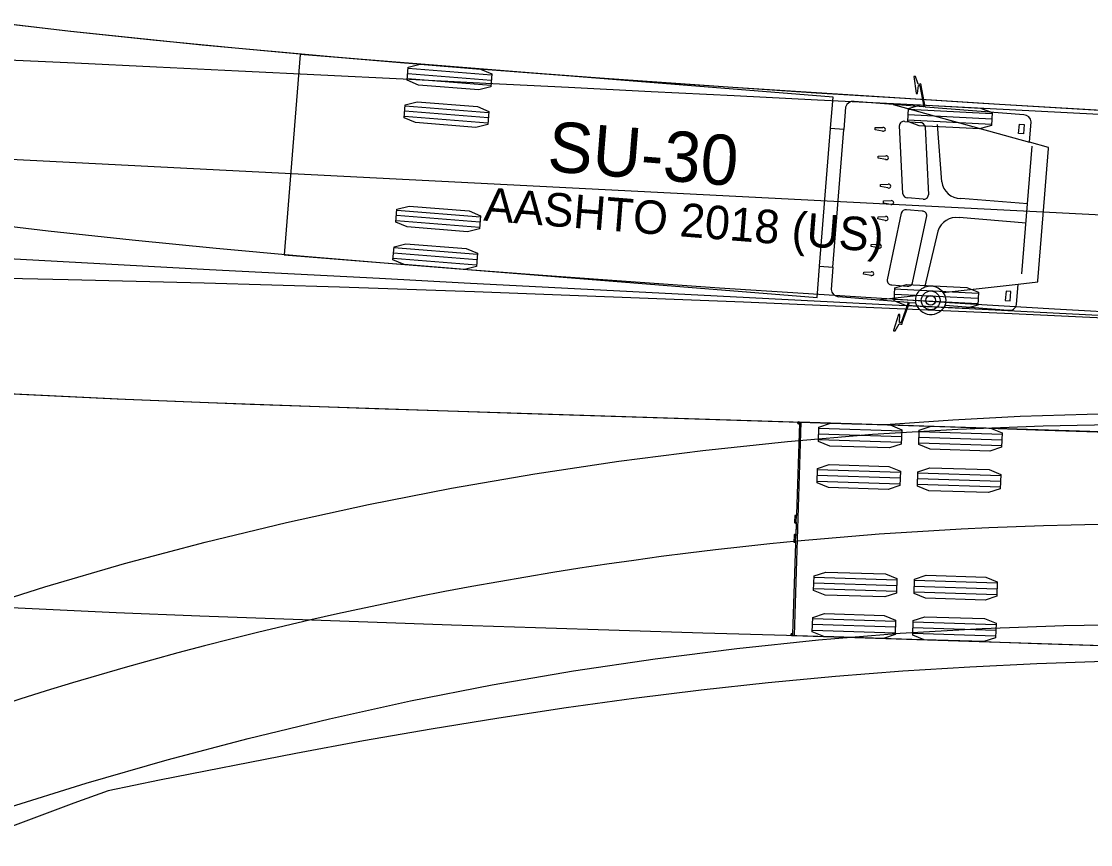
# Model space of a CAD drawing. Extents: x 260275 to 261282, y 610916 to 614143.
# Drawn here: x 261085.23 to 261127.81, y 611586.21 to 611618.98 of the extents above; entities that cross this region are included whole.
import ezdxf

# ---------------------------------------------------------------- set-up
doc = ezdxf.new("R2010")
doc.units = 0
doc.layers.add('UT_X_Water_Cells', color=7, linetype='Continuous')

msp = doc.modelspace()

# ---------------------------------------------------------------- linework, layer by layer
at = {"layer": 'UT_X_Water_Cells'}
for p, q in [((261103.944, 611616.631), (261100.621, 611616.896)), ((261103.96, 611616.838), (261100.637, 611617.103)), ((261103.927, 611616.423), (261100.604, 611616.688)), ((261103.841, 611615.343), (261100.518, 611615.608)), ((261119.945, 611615.672), (261125.371, 611614.171)), ((261103.808, 611614.928), (261100.485, 611615.193)), ((261103.824, 611615.135), (261100.502, 611615.4)), ((261123.871, 611615.089), (261120.542, 611615.258)), ((261123.882, 611615.297), (261120.553, 611615.466)), ((261119.227, 611614.667), (261119.234, 611614.75)), ((261119.234, 611614.75), (261119.536, 611614.761)), ((261120.333, 611612.119), (261120.196, 611614.833)), ((261120.412, 611614.998), (261121.027, 611614.949)), ((261123.861, 611614.881), (261120.532, 611615.05)), ((261121.216, 611614.782), (261121.352, 611612.068)), ((261121.882, 611612.59), (261121.718, 611614.874)), ((261124.941, 611614.517), (261124.972, 611614.894)), ((261124.972, 611614.894), (261125.165, 611614.879)), ((261125.165, 611614.879), (261125.135, 611614.501)), ((261066.343, 611614.434), (261269.731, 611604.069)), ((261117.017, 611609.238), (261117.454, 611614.713)), ((261117.547, 611609.196), (261117.984, 611614.671)), ((261119.523, 611614.608), (261119.227, 611614.667)), ((261125.135, 611614.501), (261124.941, 611614.517)), ((261125.076, 611608.923), (261125.482, 611614.012)), ((261119.348, 611613.537), (261119.355, 611613.619)), ((261119.658, 611613.477), (261119.348, 611613.537)), ((261119.355, 611613.619), (261119.67, 611613.631)), ((261119.441, 611612.409), (261119.448, 611612.491)), ((261119.737, 611612.349), (261119.441, 611612.409)), ((261119.448, 611612.491), (261119.749, 611612.503)), ((261119.557, 611611.749), (261119.564, 611611.831)), ((261119.853, 611611.689), (261119.557, 611611.749)), ((261119.564, 611611.831), (261119.866, 611611.843)), ((261121.137, 611611.903), (261120.522, 611611.952)), ((261125.299, 611611.717), (261122.639, 611611.929)), ((261103.51, 611611.19), (261100.187, 611611.455)), ((261120.271, 611611.343), (261119.706, 611608.685)), ((261121.099, 611611.429), (261120.484, 611611.478)), ((261103.476, 611610.774), (261100.154, 611611.039)), ((261103.493, 611610.982), (261100.17, 611611.247)), ((261119.338, 611611.116), (261119.345, 611611.199)), ((261119.634, 611611.057), (261119.338, 611611.116)), ((261119.345, 611611.199), (261119.646, 611611.211)), ((261120.721, 611608.574), (261121.286, 611611.232)), ((261125.238, 611610.953), (261122.578, 611611.166)), ((261121.726, 611610.633), (261121.199, 611608.392)), ((261119.067, 611610.017), (261119.074, 611610.099)), ((261119.074, 611610.099), (261119.376, 611610.111)), ((261103.374, 611609.487), (261100.051, 611609.752)), ((261103.39, 611609.694), (261100.068, 611609.959)), ((261119.363, 611609.958), (261119.067, 611610.017)), ((261103.357, 611609.279), (261100.034, 611609.544)), ((261118.769, 611608.92), (261118.775, 611609.002)), ((261119.065, 611608.861), (261118.769, 611608.92)), ((261118.775, 611609.002), (261119.077, 611609.014)), ((261119.893, 611608.488), (261120.508, 611608.439)), ((261121.943, 611608.188), (261124.92, 611608.518)), ((261119.325, 611607.897), (261120.865, 611608.068)), ((261123.325, 611607.943), (261119.996, 611608.113)), ((261123.336, 611608.151), (261120.007, 611608.321)), ((261124.441, 611608.245), (261124.411, 611607.868)), ((261124.635, 611608.23), (261124.441, 611608.245)), ((261124.605, 611607.852), (261124.635, 611608.23)), ((261123.315, 611607.735), (261119.986, 611607.905)), ((261122.019, 611607.682), (261124.533, 611607.481)), ((261124.411, 611607.868), (261124.605, 611607.852)), ((261116.013, 611594.53), (261116.286, 611603.026)), ((261120.278, 611602.439), (261116.98, 611602.545)), ((261120.286, 611602.668), (261116.988, 611602.774)), ((261124.276, 611602.31), (261120.978, 611602.416)), ((261124.284, 611602.539), (261120.985, 611602.645)), ((261120.271, 611602.21), (261116.973, 611602.316)), ((261124.269, 611602.081), (261120.971, 611602.187)), ((261120.233, 611601.019), (261116.935, 611601.125)), ((261120.225, 611600.79), (261116.927, 611600.896)), ((261124.223, 611600.661), (261120.925, 611600.767)), ((261124.231, 611600.89), (261120.932, 611600.996)), ((261120.218, 611600.561), (261116.92, 611600.667)), ((261124.216, 611600.432), (261120.918, 611600.538)), ((261116.088, 611599.04), (261116.071, 611598.517)), ((261116.088, 611599.046), (261116.096, 611599.311)), ((261116.079, 611598.78), (261116.15, 611598.778)), ((261116.062, 611598.249), (261116.071, 611598.515)), ((261120.095, 611596.738), (261116.797, 611596.844)), ((261120.088, 611596.509), (261116.79, 611596.615)), ((261124.086, 611596.38), (261120.787, 611596.486)), ((261124.093, 611596.609), (261120.795, 611596.715)), ((261120.08, 611596.28), (261116.782, 611596.386)), ((261124.078, 611596.151), (261120.78, 611596.257)), ((261120.042, 611595.089), (261116.744, 611595.195)), ((261120.027, 611594.63), (261116.729, 611594.736)), ((261120.035, 611594.859), (261116.737, 611594.966)), ((261124.033, 611594.731), (261120.734, 611594.837)), ((261124.04, 611594.96), (261120.742, 611595.066)), ((261124.025, 611594.502), (261120.727, 611594.608))]:
    msp.add_line(p, q, dxfattribs=at)
for points in [[(261083.936, 611618.979), (261087.195, 611618.596), (261090.467, 611618.245), (261093.749, 611617.921), (261097.038, 611617.62), (261100.335, 611617.339), (261103.637, 611617.075), (261106.943, 611616.825), (261110.253, 611616.587), (261113.566, 611616.359), (261116.881, 611616.141), (261120.199, 611615.93), (261123.519, 611615.725), (261126.839, 611615.525), (261130.162, 611615.33)], [(261084.592, 611618.899), (261087.2, 611618.596), (261092.438, 611618.047), (261097.699, 611617.562), (261102.977, 611617.126), (261108.268, 611616.728), (261113.567, 611616.359), (261124.183, 611615.684), (261134.814, 611615.063), (261156.1, 611613.904), (261198.699, 611611.699)], [(261084.127, 611617.473), (261087.366, 611617.325), (261090.618, 611617.171), (261093.882, 611617.013), (261097.154, 611616.853), (261100.436, 611616.69), (261103.724, 611616.526), (261107.018, 611616.36), (261110.318, 611616.194), (261113.622, 611616.027), (261116.929, 611615.859), (261120.24, 611615.691), (261123.554, 611615.522), (261126.87, 611615.354), (261130.188, 611615.185)], [(261118.055, 611615.567), (261117.984, 611614.674), (261117.98, 611614.671), (261117.455, 611614.713), (261117.455, 611614.724), (261117.553, 611615.963), (261096.334, 611617.656), (261096.016, 611613.668), (261095.698, 611609.681), (261116.917, 611607.988), (261117.016, 611609.227), (261117.018, 611609.238), (261117.543, 611609.196), (261117.547, 611609.193), (261117.476, 611608.3)], [(261120.993, 611616.471), (261120.946, 611616.475), (261120.945, 611616.476), (261120.838, 611616.78), (261120.773, 611616.785), (261120.773, 611616.782), (261120.859, 611616.117), (261120.86, 611616.114), (261120.916, 611616.11), (261120.916, 611616.112), (261120.95, 611616.428), (261120.95, 611616.429), (261120.994, 611616.424)], [(261125.154, 611615.257), (261121.233, 611615.569), (261121.222, 611615.577), (261121.062, 611616.424), (261121.062, 611616.425)], [(261121.014, 611616.412), (261121.014, 611616.411), (261121.168, 611615.579), (261121.155, 611615.575), (261118.39, 611615.796)], [(261124.856, 611607.71), (261124.92, 611608.515), (261124.925, 611608.519), (261125.706, 611608.606), (261125.711, 611608.648), (261125.921, 611611.283), (261126.131, 611613.918), (261126.133, 611613.96), (261125.376, 611614.17), (261125.371, 611614.175), (261125.436, 611614.98)], [(261082.953, 611611.04), (261086.299, 611610.647), (261089.645, 611610.287), (261092.99, 611609.957), (261096.333, 611609.651), (261099.675, 611609.366), (261103.015, 611609.099), (261106.354, 611608.846), (261109.692, 611608.607), (261113.028, 611608.378), (261116.364, 611608.158), (261119.698, 611607.945), (261123.032, 611607.739), (261126.365, 611607.539), (261129.697, 611607.344)], [(261082.504, 611609.665), (261085.925, 611609.474), (261089.332, 611609.288), (261092.728, 611609.107), (261096.113, 611608.928), (261099.491, 611608.751), (261102.86, 611608.576), (261106.224, 611608.402), (261109.582, 611608.23), (261112.936, 611608.057), (261116.286, 611607.886), (261119.633, 611607.715), (261122.977, 611607.544), (261126.319, 611607.373), (261129.658, 611607.203)], [(261188.635, 611604.191), (261146.014, 611606.327), (261124.68, 611607.337), (261113.994, 611607.802), (261103.282, 611608.218), (261097.908, 611608.4), (261092.517, 611608.561), (261087.099, 611608.697), (261081.645, 611608.809)], [(261117.77, 611608.021), (261120.535, 611607.8), (261120.547, 611607.794), (261120.263, 611606.997), (261120.263, 611606.997)], [(261120.309, 611606.976), (261120.309, 611606.977), (261120.6, 611607.788), (261120.613, 611607.794), (261120.84, 611607.776)], [(261120.242, 611606.987), (261120.198, 611606.99), (261120.197, 611606.991), (261120.214, 611607.308), (261120.214, 611607.31), (261120.158, 611607.315), (261120.157, 611607.312), (261119.966, 611606.669), (261119.966, 611606.666), (261120.03, 611606.661), (261120.185, 611606.945), (261120.186, 611606.945), (261120.233, 611606.942)], [(261082.788, 611604.259), (261086.071, 611604.093), (261089.369, 611603.944), (261092.677, 611603.81), (261095.993, 611603.685), (261099.315, 611603.569), (261102.642, 611603.458), (261105.971, 611603.35), (261109.303, 611603.245), (261112.637, 611603.14), (261115.972, 611603.035), (261119.308, 611602.929), (261122.645, 611602.821), (261125.982, 611602.712), (261129.32, 611602.6)], [(261083.782, 611604.207), (261089.045, 611603.958), (261094.338, 611603.746), (261104.974, 611603.382), (261118.308, 611602.962), (261119.643, 611602.935), (261122.321, 611603.122), (261124.998, 611603.258), (261127.674, 611603.345), (261130.349, 611603.384), (261133.023, 611603.374), (261135.695, 611603.316), (261138.365, 611603.211), (261141.033, 611603.058), (261151.703, 611602.341), (261162.373, 611601.688), (261170.375, 611601.234), (261181.049, 611600.761)], [(261083.033, 611595.474), (261086.164, 611596.467), (261089.337, 611597.392), (261092.547, 611598.247), (261095.789, 611599.033), (261099.061, 611599.75), (261102.359, 611600.395), (261105.679, 611600.97), (261109.019, 611601.472), (261112.375, 611601.902), (261115.745, 611602.258), (261119.127, 611602.541), (261122.518, 611602.749), (261125.917, 611602.883), (261129.32, 611602.942)], [(261115.943, 611594.555), (261115.943, 611594.532), (261163.847, 611592.993), (261163.984, 611597.24), (261164.121, 611601.488), (261116.216, 611603.028), (261116.215, 611603.006)], [(261116.214, 611602.982), (261116.214, 611602.981), (261116.098, 611599.347), (261116.096, 611599.311), (261116.026, 611599.313), (261116.026, 611599.312), (261116.017, 611599.046)], [(261116, 611598.519), (261115.992, 611598.253), (261115.992, 611598.252), (261116.062, 611598.249), (261116.061, 611598.213), (261115.944, 611594.58), (261115.944, 611594.579)], [(261082.326, 611595.772), (261085.664, 611595.603), (261089.004, 611595.452), (261092.345, 611595.316), (261095.686, 611595.191), (261099.025, 611595.074), (261102.363, 611594.962), (261105.7, 611594.855), (261109.035, 611594.749), (261112.37, 611594.644), (261115.704, 611594.539), (261119.037, 611594.433), (261122.369, 611594.326), (261125.701, 611594.216), (261129.033, 611594.105)], [(261084.586, 611587.644), (261087.813, 611588.648), (261091.04, 611589.579), (261094.269, 611590.436), (261097.5, 611591.219), (261100.735, 611591.927), (261103.975, 611592.561), (261107.218, 611593.121), (261110.466, 611593.607), (261113.717, 611594.019), (261116.971, 611594.357), (261120.227, 611594.622), (261123.485, 611594.814), (261126.742, 611594.933), (261129.999, 611594.979)], [(261176.331, 611592.251), (261165.672, 611592.71), (261155.013, 611593.147), (261144.355, 611593.559), (261139.021, 611593.616), (261133.684, 611593.602), (261131.015, 611593.563), (261128.345, 611593.497), (261125.674, 611593.402), (261123.002, 611593.274), (261120.328, 611593.107), (261117.653, 611592.897), (261114.976, 611592.646), (261112.297, 611592.353), (261109.616, 611592.021), (261106.932, 611591.652), (261104.246, 611591.246), (261101.555, 611590.808), (261098.86, 611590.337), (261096.16, 611589.839), (261090.739, 611588.77), (261088.696, 611588.35), (261087.322, 611587.861), (261084.559, 611586.816)]]:
    msp.add_lwpolyline(points, dxfattribs=at)
for points in [[(261103.964, 611616.89), (261103.923, 611616.371), (261103.445, 611616.252), (261101.053, 611616.443), (261100.6, 611616.637), (261100.641, 611617.155), (261101.119, 611617.274), (261103.512, 611617.083)], [(261103.845, 611615.395), (261103.804, 611614.876), (261103.326, 611614.757), (261100.934, 611614.948), (261100.481, 611615.141), (261100.522, 611615.66), (261101, 611615.779), (261103.392, 611615.588)], [(261123.885, 611615.349), (261123.858, 611614.829), (261123.384, 611614.697), (261120.987, 611614.819), (261120.529, 611614.999), (261120.556, 611615.518), (261121.03, 611615.651), (261123.427, 611615.529)], [(261103.514, 611611.241), (261103.472, 611610.723), (261102.995, 611610.604), (261100.602, 611610.795), (261100.15, 611610.988), (261100.191, 611611.506), (261100.669, 611611.625), (261103.061, 611611.434)], [(261103.394, 611609.746), (261103.353, 611609.228), (261102.875, 611609.108), (261100.483, 611609.299), (261100.03, 611609.493), (261100.072, 611610.011), (261100.549, 611610.13), (261102.942, 611609.939)], [(261123.339, 611608.203), (261123.312, 611607.683), (261122.838, 611607.551), (261120.441, 611607.673), (261119.983, 611607.854), (261120.01, 611608.373), (261120.484, 611608.506), (261122.881, 611608.383)], [(261120.288, 611602.725), (261120.269, 611602.153), (261119.802, 611601.996), (261117.427, 611602.072), (261116.971, 611602.259), (261116.989, 611602.831), (261117.457, 611602.988), (261119.831, 611602.912)], [(261124.286, 611602.596), (261124.267, 611602.025), (261123.8, 611601.867), (261121.425, 611601.943), (261120.969, 611602.131), (261120.987, 611602.702), (261121.455, 611602.86), (261123.829, 611602.783)], [(261120.235, 611601.076), (261120.216, 611600.504), (261119.749, 611600.347), (261117.374, 611600.423), (261116.918, 611600.61), (261116.936, 611601.182), (261117.404, 611601.339), (261119.778, 611601.263)], [(261124.233, 611600.947), (261124.214, 611600.375), (261123.747, 611600.218), (261121.372, 611600.294), (261120.916, 611600.481), (261120.934, 611601.053), (261121.402, 611601.211), (261123.776, 611601.134)], [(261120.097, 611596.794), (261120.079, 611596.223), (261119.611, 611596.065), (261117.237, 611596.142), (261116.78, 611596.329), (261116.799, 611596.901), (261117.266, 611597.058), (261119.641, 611596.982)], [(261124.095, 611596.666), (261124.077, 611596.094), (261123.609, 611595.937), (261121.234, 611596.013), (261120.778, 611596.2), (261120.797, 611596.772), (261121.264, 611596.929), (261123.639, 611596.853)], [(261120.044, 611595.145), (261120.026, 611594.574), (261119.558, 611594.416), (261117.184, 611594.493), (261116.727, 611594.68), (261116.746, 611595.251), (261117.213, 611595.409), (261119.588, 611595.332)], [(261124.042, 611595.017), (261124.024, 611594.445), (261123.556, 611594.288), (261121.181, 611594.364), (261120.725, 611594.551), (261120.744, 611595.123), (261121.211, 611595.28), (261123.586, 611595.204)]]:
    msp.add_lwpolyline(points, close=True, dxfattribs=at)
for centre, radius in [((261121.441, 611607.873), 0.374), ((261121.441, 611607.873), 0.193), ((261116.181, 611602.995), 0.0266), ((261115.91, 611594.568), 0.0266)]:
    msp.add_circle(centre, radius, dxfattribs=at)
for centre, radius, start, end in [((261121.027, 611616.447), 0.0418, 327.9314, 144.9463), ((261121.027, 611616.453), 0.0434, 220.8532, 251.526), ((261118.364, 611615.474), 0.323, 85.4395, 163.2879), ((261125.154, 611614.975), 0.282, 0.9879, 90.0673), ((261119.547, 611614.671), 0.091, 2.9591, 97.1229), ((261120.38, 611614.817), 0.184, 79.9757, 174.8469), ((261121.025, 611614.756), 0.193, 7.5819, 89.4964), ((261119.549, 611614.695), 0.0909, 253.7204, 347.9556), ((261119.67, 611613.565), 0.0909, 253.7204, 347.9556), ((261119.668, 611613.541), 0.091, 2.9591, 97.1229), ((261119.763, 611612.436), 0.0909, 253.7204, 347.9556), ((261119.761, 611612.413), 0.091, 2.9591, 97.1229), ((261122.647, 611612.702), 0.773, 188.33, 269.4141), ((261119.879, 611611.777), 0.091, 253.7561, 347.9199), ((261119.877, 611611.753), 0.091, 2.9591, 97.1229), ((261120.523, 611612.145), 0.193, 187.577, 269.5013), ((261121.169, 611612.085), 0.184, 259.9812, 354.8414), ((261120.455, 611611.288), 0.193, 81.3777, 163.302), ((261121.102, 611611.245), 0.184, 356.0376, 90.8978), ((261119.659, 611611.144), 0.091, 253.7561, 347.9199), ((261119.658, 611611.12), 0.0909, 2.9234, 97.1586), ((261122.463, 611610.401), 0.773, 81.4649, 162.549), ((261119.387, 611610.021), 0.0909, 2.9234, 97.1586), ((261119.389, 611610.045), 0.091, 253.7561, 347.9199), ((261119.09, 611608.948), 0.091, 253.7561, 347.9199), ((261119.089, 611608.924), 0.0909, 2.9234, 97.1586), ((261119.89, 611608.672), 0.184, 176.0321, 270.9033), ((261120.536, 611608.629), 0.193, 261.3826, 343.2971), ((261121.429, 611607.805), 0.63, 84.7943, 137.1971), ((261121.444, 611607.805), 0.629, 37.4851, 86.1744), ((261117.795, 611608.342), 0.323, 187.5911, 265.4395), ((261121.354, 611607.88), 0.524, 137.6985, 191.4986), ((261121.527, 611607.867), 0.526, 339.3847, 37.6307), ((261121.447, 611607.94), 0.628, 195.1928, 335.6845), ((261124.578, 611607.759), 0.282, 260.8117, 349.8911), ((261120.27, 611606.96), 0.0418, 205.9326, 22.9476), ((261120.27, 611606.954), 0.0434, 99.353, 130.0258), ((261116.181, 611602.995), 0.0363, 17.2356, 338.3982), ((261116.053, 611599.045), 0.0352, 357.9463, 180.5857), ((261116.053, 611599.045), 0.0352, 178.1744, 358.7609), ((261130.35, 611448.962), 150, 87.08254, 113.79918), ((261116.036, 611598.518), 0.0352, 357.5567, 178.1432), ((261116.036, 611598.518), 0.0354, 182.4503, 354.6358), ((261115.91, 611594.568), 0.0363, 17.9194, 339.082)]:
    msp.add_arc(centre, radius, start, end, dxfattribs=at)

# ---------------------------------------------------------------- texts
for s, height, p in [('SU-30', 2, (261106.14, 611613.021)), ('AASHTO 2018 (US)', 1.33333, (261103.618, 611611.049))]:
    msp.add_text(s, height=height, rotation=355.4395, dxfattribs=at).set_placement(p)

doc.saveas('drawing.dxf')
